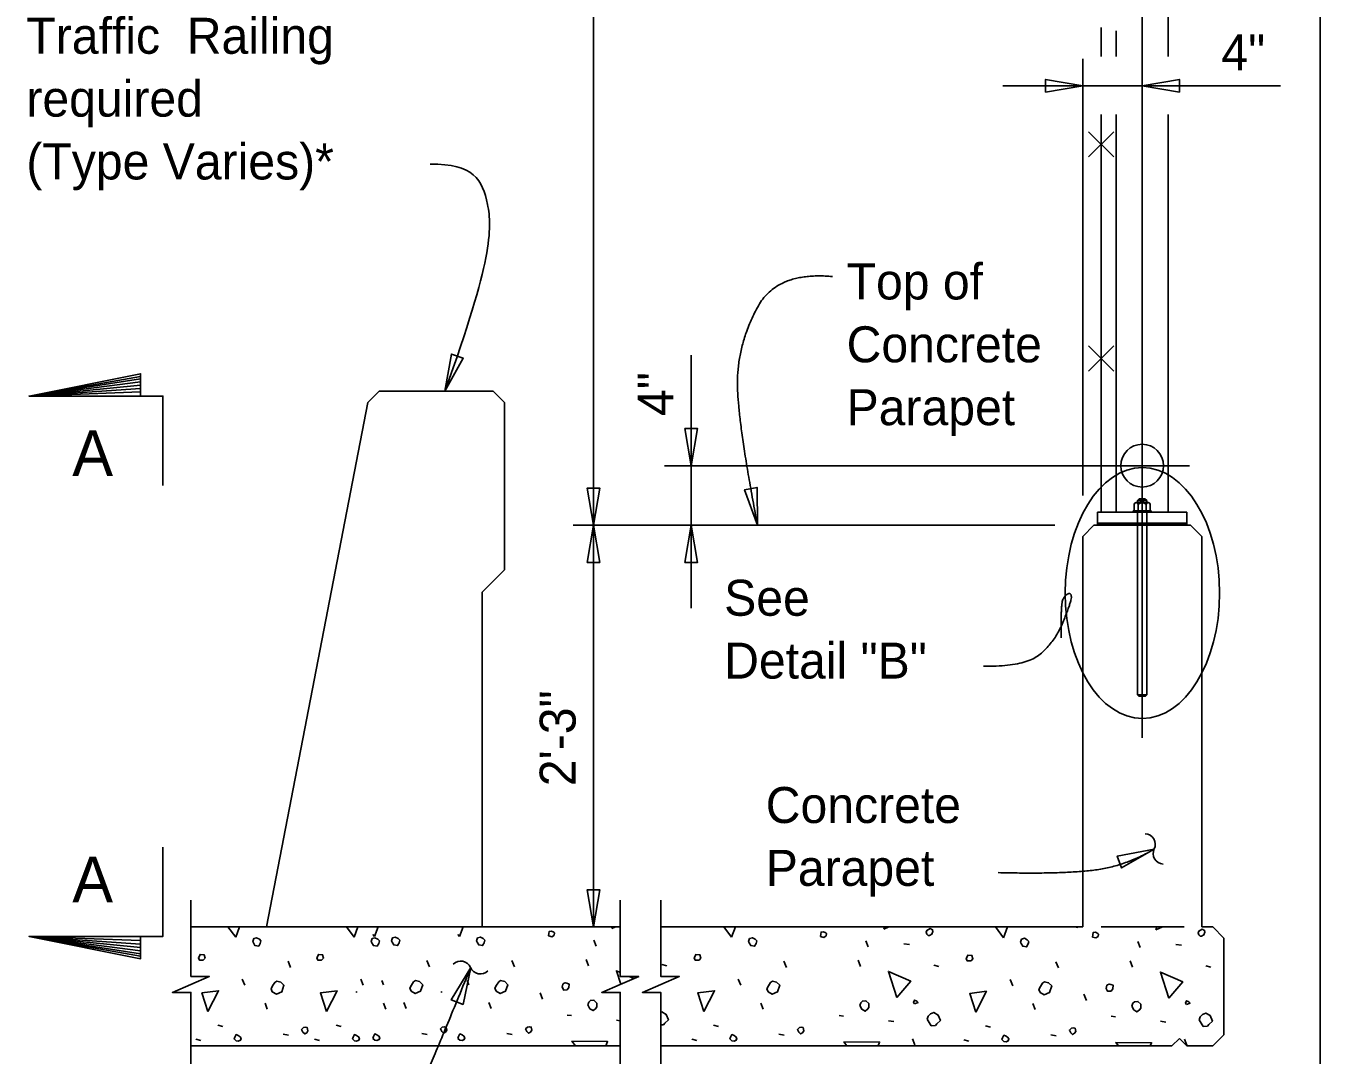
# Model space of a CAD drawing. Extents: x 0 to 72.1, y -15.2 to 30.1.
# Drawn here: x 33.82 to 41.07, y 15.56 to 21.32 of the extents above; entities that cross this region are included whole.
import ezdxf

# ---------------------------------------------------------------- set-up
doc = ezdxf.new("R2010")
doc.units = 0
for name, color, linetype in [('ActivePts-ConstElements', 7, 'Continuous'), ('AdhocPoint_dp', 7, 'Continuous'), ('Border', 7, 'Continuous'), ('Patterning', 7, 'Continuous'), ('PlotBorder_dp', 7, 'Continuous'), ('SheetBorder_dp', 7, 'Continuous'), ('SheetLines_dp', 7, 'Continuous'), ('SupstrConc_h', 7, 'Continuous'), ('TextMisc', 7, 'Continuous')]:
    doc.layers.add(name, color=color, linetype=linetype)

# ---------------------------------------------------------------- blocks, each defined once
blk = doc.blocks.new('Terminator-Arrow')
at = {"layer": 'PlotBorder_dp'}
blk.add_lwpolyline([(0, 0), (-0.00041, 0.000069), (-0.00041, -0.000069), (0, 0)], dxfattribs=at)
blk.add_lwpolyline([(0, 0), (-0.00041, 0.000069), (-0.00041, -0.000069)], close=True, dxfattribs=at)

msp = doc.modelspace()

# ---------------------------------------------------------------- linework, layer by layer
at = {"layer": 'ActivePts-ConstElements'}
msp.add_lwpolyline([(0.016, 2.0538), (41.0666, 2.0538), (41.0666, 27.9999), (0.016, 27.9999)], close=True, dxfattribs=at)
at = {"layer": 'AdhocPoint_dp'}
for p, q in [((39.7989, 18.5283), (39.7364, 18.465)), ((40.3405, 18.5283), (39.7989, 18.5283)), ((40.3405, 18.5283), (39.7989, 18.5283)), ((40.3405, 18.5283), (40.4031, 18.465)), ((39.7364, 16.2784), (39.7364, 18.465)), ((40.4031, 16.2784), (40.4031, 18.465)), ((34.7399, 16.2784), (37.1456, 16.2784)), ((37.3729, 16.2784), (39.7364, 16.2784)), ((40.4031, 16.2784), (40.4656, 16.2784)), ((40.4656, 16.2784), (40.5281, 16.2159)), ((40.5281, 16.2159), (40.5281, 15.6742)), ((40.5281, 15.6742), (40.4656, 15.6117)), ((40.2364, 15.6117), (37.3729, 15.6117)), ((40.2364, 15.6117), (40.2781, 15.6533)), ((40.2781, 15.6533), (40.3198, 15.6117)), ((40.4656, 15.6117), (40.3198, 15.6117))]:
    msp.add_line(p, q, dxfattribs=at)
at = {"layer": 'Border'}
for p, q in [((40.0437, 18.6013), (40.0437, 17.5781)), ((40.0958, 18.6013), (40.0958, 17.5781)), ((40.0437, 17.5781), (40.0958, 17.5781)), ((40.0437, 17.5781), (40.0519, 17.57)), ((40.0519, 17.57), (40.0876, 17.57)), ((40.0958, 17.5781), (40.0876, 17.57))]:
    msp.add_line(p, q, dxfattribs=at)
at = {"layer": 'Patterning'}
for p, q in [((39.9112, 20.7323), (39.7698, 20.5911)), ((39.7698, 20.7323), (39.9112, 20.5911)), ((39.9112, 19.5323), (39.7698, 19.3911)), ((39.7698, 19.5323), (39.9112, 19.3911)), ((40.0586, 18.6707), (40.0793, 18.6707)), ((40.0586, 18.661), (40.0793, 18.661)), ((39.8197, 18.5353), (40.3197, 18.5353)), ((39.8197, 18.5318), (40.3197, 18.5318)), ((35.4069, 16.2784), (35.4083, 16.2781)), ((38.185, 16.2784), (38.1863, 16.2781)), ((39.6911, 16.2784), (39.7101, 16.2746)), ((37.0108, 16.1703), (36.9984, 16.2039)), ((38.5346, 16.1667), (38.5222, 16.2003)), ((38.7343, 16.1826), (38.7662, 16.1791)), ((40.0584, 16.1632), (40.046, 16.1968)), ((40.2581, 16.1791), (40.29, 16.1756)), ((35.2987, 16.0518), (35.2845, 16.0872)), ((36.0762, 16.0554), (36.0621, 16.0907)), ((36.5529, 16.0554), (36.5388, 16.0907)), ((36.9683, 16.0607), (36.9542, 16.096)), ((37.3785, 16.0677), (37.4067, 16.0607)), ((38.0767, 16.0518), (38.0626, 16.0872)), ((38.4922, 16.0571), (38.478, 16.0925)), ((38.9023, 16.0642), (38.9306, 16.0571)), ((39.6005, 16.0483), (39.5864, 16.0836)), ((40.016, 16.0536), (40.0018, 16.0889)), ((40.4261, 16.0607), (40.4544, 16.0536)), ((35.0424, 15.9511), (35.0282, 15.9864)), ((35.7059, 15.9511), (35.6917, 15.9864)), ((35.8199, 15.9546), (35.8104, 15.9783)), ((36.2966, 15.9546), (36.2871, 15.9783)), ((37.8204, 15.9511), (37.8063, 15.9864)), ((39.3442, 15.9475), (39.3301, 15.9829)), ((36.7102, 15.8733), (36.6961, 15.9086)), ((39.7579, 15.8662), (39.7437, 15.9016)), ((35.1679, 15.8185), (35.1555, 15.8521)), ((35.8314, 15.8185), (35.819, 15.8521)), ((35.9454, 15.822), (35.933, 15.8556)), ((36.4221, 15.822), (36.4097, 15.8556)), ((37.9459, 15.8185), (37.9335, 15.8521)), ((39.4697, 15.8149), (39.4573, 15.8485)), ((36.8481, 15.7849), (36.8729, 15.7814)), ((37.1239, 15.7566), (37.1456, 15.7528)), ((38.3719, 15.7814), (38.3967, 15.7778)), ((38.6477, 15.7531), (38.6778, 15.7478)), ((39.8958, 15.7778), (39.9205, 15.7743)), ((40.1715, 15.7495), (40.2016, 15.7442)), ((34.8903, 15.7283), (34.9186, 15.7213)), ((35.2563, 15.6771), (35.2863, 15.6718)), ((35.5538, 15.7283), (35.5821, 15.7213)), ((36.0338, 15.6806), (36.0639, 15.6753)), ((36.5105, 15.6806), (36.5405, 15.6753)), ((37.6684, 15.7283), (37.6967, 15.7213)), ((38.0343, 15.6771), (38.0644, 15.6718)), ((39.1922, 15.7248), (39.2205, 15.7177)), ((39.5581, 15.6735), (39.5882, 15.6682)), ((34.7684, 15.6488), (34.7966, 15.6417)), ((35.4319, 15.6488), (35.4601, 15.6417)), ((37.5464, 15.6488), (37.5747, 15.6417)), ((38.7962, 15.6187), (38.7838, 15.6523)), ((39.0702, 15.6452), (39.0985, 15.6382)), ((40.32, 15.6152), (40.3076, 15.6488))]:
    msp.add_line(p, q, dxfattribs=at)
for points in [[(39.8406, 21.3159), (39.8406, 21.1537)], [(39.8406, 20.8291), (39.8406, 18.6013)], [(34.9911, 16.2215), (34.9479, 16.2784)], [(35.0123, 16.2784), (34.9911, 16.2215)], [(35.6546, 16.2215), (35.6114, 16.2784)], [(35.6758, 16.2784), (35.6546, 16.2215)], [(35.7886, 16.2784), (35.7686, 16.2251)], [(36.2652, 16.2784), (36.2453, 16.2251)], [(36.7438, 16.2286), (36.7633, 16.2233), (36.7757, 16.2321), (36.7774, 16.2445), (36.7739, 16.248), (36.7597, 16.2551), (36.7474, 16.2534), (36.7456, 16.241), (36.7438, 16.2286)], [(37.0992, 16.2693), (37.102, 16.2784)], [(37.1194, 16.2784), (37.0992, 16.2693)], [(37.3729, 16.2562), (37.3732, 16.2569), (37.3729, 16.2581)], [(37.7691, 16.2215), (37.7259, 16.2784)], [(37.7904, 16.2784), (37.7691, 16.2215)], [(38.2676, 16.2251), (38.2871, 16.2198), (38.2995, 16.2286), (38.3012, 16.241), (38.2977, 16.2445), (38.2836, 16.2516), (38.2712, 16.2498), (38.2694, 16.2374), (38.2676, 16.2251)], [(38.623, 16.2657), (38.6269, 16.2784)], [(38.6511, 16.2784), (38.623, 16.2657)], [(38.8705, 16.2304), (38.8775, 16.2304), (38.8917, 16.2374), (38.897, 16.2534), (38.8952, 16.2622), (38.8811, 16.2693), (38.8634, 16.2587), (38.8598, 16.248), (38.8634, 16.2374), (38.8705, 16.2304)], [(39.2929, 16.218), (39.2471, 16.2784)], [(39.3155, 16.2784), (39.2929, 16.218)], [(39.7915, 16.2215), (39.8109, 16.2162), (39.8233, 16.2251), (39.825, 16.2374), (39.8215, 16.241), (39.8074, 16.248), (39.795, 16.2463), (39.7932, 16.2339), (39.7915, 16.2215)], [(40.1468, 16.2622), (40.1518, 16.2784)], [(40.1828, 16.2784), (40.1468, 16.2622)], [(40.3943, 16.2268), (40.4013, 16.2268), (40.4155, 16.2339), (40.4208, 16.2498), (40.419, 16.2587), (40.4049, 16.2657), (40.3872, 16.2551), (40.3837, 16.2445), (40.3872, 16.2339), (40.3943, 16.2268)], [(35.0901, 16.1897), (35.0989, 16.1738), (35.1201, 16.1703), (35.129, 16.1862), (35.1325, 16.2003), (35.1237, 16.2092), (35.1078, 16.218), (35.0919, 16.2127), (35.0866, 16.1968), (35.0901, 16.1897)], [(35.7536, 16.1897), (35.7624, 16.1738), (35.7836, 16.1703), (35.7925, 16.1862), (35.796, 16.2003), (35.7872, 16.2092), (35.7713, 16.218), (35.7554, 16.2127), (35.7501, 16.1968), (35.7536, 16.1897)], [(35.7686, 16.2251), (35.7598, 16.2367)], [(35.8676, 16.1932), (35.8765, 16.1773), (35.8977, 16.1738), (35.9065, 16.1897), (35.9101, 16.2039), (35.9012, 16.2127), (35.8853, 16.2215), (35.8694, 16.2162), (35.8641, 16.2003), (35.8676, 16.1932)], [(36.2453, 16.2251), (36.2365, 16.2367)], [(36.3443, 16.1932), (36.3532, 16.1773), (36.3744, 16.1738), (36.3832, 16.1897), (36.3867, 16.2039), (36.3779, 16.2127), (36.362, 16.2215), (36.3461, 16.2162), (36.3408, 16.2003), (36.3443, 16.1932)], [(37.8681, 16.1897), (37.877, 16.1738), (37.8982, 16.1703), (37.907, 16.1862), (37.9106, 16.2003), (37.9017, 16.2092), (37.8858, 16.218), (37.8699, 16.2127), (37.8646, 16.1968), (37.8681, 16.1897)], [(39.3919, 16.1862), (39.4008, 16.1703), (39.422, 16.1667), (39.4308, 16.1826), (39.4344, 16.1968), (39.4255, 16.2056), (39.4096, 16.2145), (39.3937, 16.2092), (39.3884, 16.1932), (39.3919, 16.1862)], [(34.7878, 16.0925), (34.809, 16.0925), (34.8196, 16.1031), (34.8143, 16.1225), (34.7913, 16.1243), (34.7878, 16.1137), (34.7825, 16.1049), (34.7878, 16.0925), (34.7843, 16.096)], [(35.4513, 16.0925), (35.4725, 16.0925), (35.4831, 16.1031), (35.4778, 16.1225), (35.4548, 16.1243), (35.4513, 16.1137), (35.446, 16.1049), (35.4513, 16.0925), (35.4478, 16.096)], [(37.5658, 16.0925), (37.5871, 16.0925), (37.5977, 16.1031), (37.5924, 16.1225), (37.5694, 16.1243), (37.5658, 16.1137), (37.5605, 16.1049), (37.5658, 16.0925), (37.5623, 16.096)], [(39.0897, 16.0889), (39.1109, 16.0889), (39.1215, 16.0996), (39.1162, 16.119), (39.0932, 16.1208), (39.0897, 16.1102), (39.0844, 16.1013), (39.0897, 16.0889), (39.0861, 16.0925)], [(37.1483, 15.9574), (37.1239, 16.0324), (37.1456, 16.0229)], [(38.6954, 15.8821), (38.6477, 16.0288), (38.7732, 15.974), (38.6954, 15.8821)], [(40.2193, 15.8786), (40.1715, 16.0253), (40.297, 15.9705), (40.2193, 15.8786)], [(35.1962, 15.9139), (35.2191, 15.9016), (35.2492, 15.9139), (35.2616, 15.9511), (35.2439, 15.9687), (35.2209, 15.974), (35.2103, 15.967), (35.1979, 15.9475), (35.1891, 15.9316), (35.1962, 15.9139)], [(35.9737, 15.9175), (35.9967, 15.9051), (36.0267, 15.9175), (36.0391, 15.9546), (36.0214, 15.9723), (35.9984, 15.9776), (35.9878, 15.9705), (35.9755, 15.9511), (35.9666, 15.9352), (35.9737, 15.9175)], [(36.4504, 15.9175), (36.4734, 15.9051), (36.5034, 15.9175), (36.5158, 15.9546), (36.4981, 15.9723), (36.4751, 15.9776), (36.4645, 15.9705), (36.4522, 15.9511), (36.4433, 15.9352), (36.4504, 15.9175)], [(36.8198, 15.9405), (36.8287, 15.9245), (36.8481, 15.9263), (36.857, 15.9387), (36.8587, 15.9581), (36.8464, 15.9634), (36.8375, 15.9652), (36.8269, 15.9617), (36.8234, 15.9581), (36.8198, 15.9405)], [(37.1952, 16.0012), (37.222, 15.9895)], [(37.9742, 15.9139), (37.9972, 15.9016), (38.0272, 15.9139), (38.0396, 15.9511), (38.0219, 15.9687), (37.9989, 15.974), (37.9883, 15.967), (37.976, 15.9475), (37.9671, 15.9316), (37.9742, 15.9139)], [(39.498, 15.9104), (39.521, 15.898), (39.551, 15.9104), (39.5634, 15.9475), (39.5457, 15.9652), (39.5228, 15.9705), (39.5122, 15.9634), (39.4998, 15.944), (39.4909, 15.9281), (39.498, 15.9104)], [(39.8675, 15.9334), (39.8763, 15.9175), (39.8958, 15.9192), (39.9046, 15.9316), (39.9064, 15.9511), (39.894, 15.9564), (39.8851, 15.9581), (39.8745, 15.9546), (39.871, 15.9511), (39.8675, 15.9334)], [(34.8355, 15.8043), (34.8019, 15.9086), (34.8956, 15.921), (34.8355, 15.8043)], [(35.499, 15.8043), (35.4654, 15.9086), (35.5591, 15.921), (35.499, 15.8043)], [(35.6692, 15.9168), (35.6663, 15.9112)], [(36.1459, 15.9168), (36.143, 15.9112)], [(37.6136, 15.8043), (37.58, 15.9086), (37.6737, 15.921), (37.6136, 15.8043)], [(39.1374, 15.8008), (39.1038, 15.9051), (39.1975, 15.9175), (39.1374, 15.8008)], [(36.9648, 15.8415), (36.9754, 15.8202), (36.9931, 15.8096), (37.0072, 15.8202), (37.0143, 15.8309), (37.0143, 15.8521), (36.9984, 15.868), (36.9789, 15.8662), (36.9701, 15.8574), (36.9648, 15.8415)], [(38.4886, 15.8379), (38.4992, 15.8167), (38.5169, 15.8061), (38.531, 15.8167), (38.5381, 15.8273), (38.5381, 15.8485), (38.5222, 15.8644), (38.5028, 15.8627), (38.4939, 15.8538), (38.4886, 15.8379)], [(38.7944, 15.8468), (38.8139, 15.8556), (38.8068, 15.8627), (38.7944, 15.868), (38.7891, 15.8556), (38.7944, 15.8468)], [(40.0124, 15.8344), (40.023, 15.8132), (40.0407, 15.8026), (40.0549, 15.8132), (40.0619, 15.8238), (40.0619, 15.845), (40.046, 15.8609), (40.0266, 15.8591), (40.0177, 15.8503), (40.0124, 15.8344)], [(40.3183, 15.8432), (40.3377, 15.8521), (40.3306, 15.8591), (40.3183, 15.8644), (40.3129, 15.8521), (40.3183, 15.8432)], [(37.3729, 15.729), (37.3873, 15.7301), (37.3961, 15.7389), (37.4156, 15.7584), (37.4032, 15.7884), (37.3785, 15.8026), (37.3729, 15.8004)], [(38.8651, 15.7619), (38.8881, 15.7248), (38.9111, 15.7266), (38.9199, 15.7354), (38.9394, 15.7548), (38.927, 15.7849), (38.9023, 15.799), (38.8846, 15.792), (38.8705, 15.7778), (38.8651, 15.7619)], [(40.389, 15.7584), (40.4119, 15.7213), (40.4349, 15.723), (40.4438, 15.7319), (40.4632, 15.7513), (40.4508, 15.7814), (40.4261, 15.7955), (40.4084, 15.7884), (40.3943, 15.7743), (40.389, 15.7584)], [(34.9929, 15.6399), (35.0052, 15.6382), (35.0176, 15.6435), (35.0211, 15.6541), (35.0158, 15.6629), (35.0052, 15.67), (34.9929, 15.6753), (34.9858, 15.6611), (34.9823, 15.6505), (34.9929, 15.6399)], [(35.3676, 15.6894), (35.3782, 15.6788), (35.3888, 15.6859), (35.3959, 15.6965), (35.3924, 15.7142), (35.3835, 15.7159), (35.3712, 15.7142), (35.3606, 15.7036), (35.3676, 15.6894)], [(35.6564, 15.6399), (35.6687, 15.6382), (35.6811, 15.6435), (35.6846, 15.6541), (35.6793, 15.6629), (35.6687, 15.67), (35.6564, 15.6753), (35.6493, 15.6611), (35.6458, 15.6505), (35.6564, 15.6399)], [(35.7704, 15.6435), (35.7828, 15.6417), (35.7952, 15.647), (35.7987, 15.6576), (35.7934, 15.6665), (35.7828, 15.6735), (35.7704, 15.6788), (35.7633, 15.6647), (35.7598, 15.6541)], [(36.1452, 15.693), (36.1558, 15.6824), (36.1664, 15.6894), (36.1735, 15.7), (36.1699, 15.7177), (36.1611, 15.7195), (36.1487, 15.7177), (36.1381, 15.7071), (36.1452, 15.693)], [(36.2471, 15.6435), (36.2595, 15.6417), (36.2718, 15.647), (36.2754, 15.6576), (36.2701, 15.6665), (36.2595, 15.6735), (36.2471, 15.6788), (36.24, 15.6647), (36.2365, 15.6541)], [(36.6219, 15.693), (36.6325, 15.6824), (36.6431, 15.6894), (36.6501, 15.7), (36.6466, 15.7177), (36.6378, 15.7195), (36.6254, 15.7177), (36.6148, 15.7071), (36.6219, 15.693)], [(37.7709, 15.6399), (37.7833, 15.6382), (37.7957, 15.6435), (37.7992, 15.6541), (37.7939, 15.6629), (37.7833, 15.67), (37.7709, 15.6753), (37.7638, 15.6611), (37.7603, 15.6505), (37.7709, 15.6399)], [(38.1457, 15.6894), (38.1563, 15.6788), (38.1669, 15.6859), (38.174, 15.6965), (38.1704, 15.7142), (38.1616, 15.7159), (38.1492, 15.7142), (38.1386, 15.7036), (38.1457, 15.6894)], [(39.2947, 15.6364), (39.3071, 15.6346), (39.3195, 15.6399), (39.323, 15.6505), (39.3177, 15.6594), (39.3071, 15.6665), (39.2947, 15.6718), (39.2876, 15.6576), (39.2841, 15.647), (39.2947, 15.6364)], [(39.6695, 15.6859), (39.6801, 15.6753), (39.6907, 15.6824), (39.6978, 15.693), (39.6942, 15.7106), (39.6854, 15.7124), (39.673, 15.7106), (39.6624, 15.7), (39.6695, 15.6859)], [(35.7598, 15.6541), (35.7704, 15.6435)], [(36.2365, 15.6541), (36.2471, 15.6435)], [(36.8948, 15.6117), (36.8746, 15.6382), (37.0744, 15.6364), (37.0652, 15.6117)], [(38.4159, 15.6117), (38.3985, 15.6346), (38.5982, 15.6329), (38.5903, 15.6117)], [(39.9371, 15.6117), (39.9223, 15.6311), (40.122, 15.6293), (40.1154, 15.6117)]]:
    msp.add_lwpolyline(points, dxfattribs=at)
msp.add_lwpolyline([(39.8197, 18.5388), (40.3197, 18.5388), (40.3197, 18.5284), (39.8197, 18.5284)], close=True, dxfattribs=at)
at = {"layer": 'PlotBorder_dp'}
for p, q in [((36.9957, 16.2784), (36.9957, 24.8617)), ((39.7364, 18.694), (39.7364, 21.1397)), ((39.2898, 20.9897), (40.8444, 20.9897)), ((37.5436, 18.063), (37.5436, 19.4799)), ((33.8335, 19.2512), (34.4585, 19.3612)), ((34.4585, 19.3479), (33.8335, 19.2512)), ((33.8335, 19.2512), (34.4585, 19.3312)), ((34.4585, 19.3129), (33.8335, 19.2512)), ((33.8335, 19.2512), (34.4585, 19.2945)), ((34.4585, 19.2745), (33.8335, 19.2512)), ((40.0697, 18.609), (40.0697, 18.6083)), ((39.5803, 18.5284), (36.8819, 18.5284)), ((34.4585, 16.2016), (33.8335, 16.2249)), ((33.8335, 16.2249), (34.4585, 16.1816)), ((34.4585, 16.1633), (33.8335, 16.2249)), ((33.8335, 16.2249), (34.4585, 16.1449)), ((34.4585, 16.1283), (33.8335, 16.2249)), ((33.8335, 16.2249), (34.4585, 16.1149))]:
    msp.add_line(p, q, dxfattribs=at)
for points in [[(39.7364, 20.9897), (39.5282, 21.025), (39.5282, 20.9544)], [(40.0697, 20.9897), (40.278, 20.9544), (40.278, 21.025)], [(37.5436, 18.8617), (37.5789, 19.0699), (37.5083, 19.0699)], [(36.9957, 18.5284), (36.9604, 18.7366), (37.031, 18.7366)], [(37.9143, 18.5284), (37.9118, 18.7396), (37.8424, 18.727)], [(36.9957, 18.5284), (36.9604, 18.3201), (37.031, 18.3201)], [(37.5436, 18.5284), (37.5083, 18.3201), (37.5789, 18.3201)], [(40.1374, 16.7145), (39.93, 16.6749), (39.9546, 16.6088)], [(36.9957, 16.2784), (37.031, 16.4866), (36.9604, 16.4866)], [(36.3076, 16.0507), (36.1991, 15.8695), (36.2649, 15.8439)]]:
    msp.add_lwpolyline(points, close=True, dxfattribs=at)
for points in [[(34.5835, 18.7512), (34.5835, 19.2512), (33.8335, 19.2512), (34.4585, 19.3762), (34.4585, 19.2512)], [(34.5835, 16.7249), (34.5835, 16.2249), (33.8335, 16.2249), (34.4585, 16.0999), (34.4585, 16.2249)], [(34.7399, 16.4284), (34.7399, 16.0012), (34.8432, 16.0012), (34.7399, 15.9562), (34.6365, 15.9112), (34.7399, 15.9112), (34.7399, 15.4617)], [(37.1456, 16.4284), (37.1456, 16.0012), (37.249, 16.0012), (37.1456, 15.9562), (37.0423, 15.9112), (37.1456, 15.9112), (37.1456, 15.4617)], [(37.3729, 16.4284), (37.3729, 16.0012), (37.4763, 16.0012), (37.3729, 15.9562), (37.2696, 15.9112), (37.3729, 15.9112), (37.3729, 15.4617)]]:
    msp.add_lwpolyline(points, dxfattribs=at)
for centre, start, end in [((40.0832, 16.7407), 334.61622, 86.34344), ((40.1909, 16.6896), 154.61622, 266.34344), ((36.252, 16.0277), 22.88008, 134.6073), ((36.3619, 16.0741), 202.88008, 314.6073)]:
    msp.add_arc(centre, 0.0596, start, end, dxfattribs=at)
msp.add_ellipse((40.071, 18.1482), major_axis=(0, 0.7024), ratio=0.61552, dxfattribs=at)
for points, degree in [([(36.0807, 20.5498), (36.3226, 20.5557), (36.4287, 20.3667), (36.4287, 20.0125), (36.1633, 19.2784)], 3), ([(38.3343, 19.9207), (38.0205, 19.9513), (37.8022, 19.5356), (37.8022, 19.1164), (37.9143, 18.5284)], 2), ([(39.1809, 17.7384), (39.4075, 17.7344), (39.578, 17.8693), (39.6731, 18.0995), (39.6731, 18.1512), (39.6359, 18.1364), (39.6137, 18.0836), (39.6151, 17.8968)], 2), ([(39.262, 16.5822), (39.6006, 16.574), (39.9722, 16.6153), (40.1374, 16.7145)], 2), ([(36.2986, 15.0134), (36.0666, 14.9967), (35.9307, 15.1557), (36.0812, 15.4988), (36.3076, 16.0507)], 2)]:
    msp.add_open_spline(points, degree=degree, dxfattribs=at)
at = {"layer": 'SheetBorder_dp'}
for p, q in [((40.0698, 17.3367), (40.0698, 21.5561)), ((37.3936, 18.8617), (40.3354, 18.8617))]:
    msp.add_line(p, q, dxfattribs=at)
at = {"layer": 'SupstrConc_h'}
for p, q in [((35.163, 16.2784), (35.7323, 19.2158)), ((35.7323, 19.2158), (35.7948, 19.2783)), ((35.7948, 19.2783), (36.4338, 19.2784)), ((36.4338, 19.2783), (36.4963, 19.2158)), ((36.4963, 19.2158), (36.4963, 18.2783)), ((36.4963, 18.2783), (36.3713, 18.1533)), ((36.3713, 18.1533), (36.3713, 16.2784)), ((40.3045, 16.2784), (39.8394, 16.2784)), ((37.1456, 15.6117), (34.7399, 15.6117))]:
    msp.add_line(p, q, dxfattribs=at)
at = {"layer": 'TextMisc'}
for p, q in [((40.2156, 21.1537), (40.2156, 24.8617)), ((39.9239, 21.1537), (39.9239, 21.2978)), ((39.9239, 18.6013), (39.9239, 20.8291)), ((40.2156, 18.6013), (40.2156, 20.8291)), ((40.0243, 18.6459), (40.0243, 18.6083)), ((40.1038, 18.6546), (40.0357, 18.6546)), ((40.0537, 18.6756), (40.044, 18.6659)), ((40.044, 18.6659), (40.044, 18.6546)), ((40.044, 18.6659), (40.0955, 18.6659)), ((40.047, 18.6462), (40.047, 18.6083)), ((40.0537, 18.6756), (40.0842, 18.6756)), ((40.0842, 18.6756), (40.0955, 18.6659)), ((40.0924, 18.6462), (40.0924, 18.6083)), ((40.0955, 18.6659), (40.0955, 18.6546)), ((40.1151, 18.6459), (40.1151, 18.6083)), ((40.0201, 18.6083), (40.0201, 18.6012)), ((40.0201, 18.6083), (40.1195, 18.6083)), ((40.1151, 18.6083), (40.0243, 18.6083)), ((40.1195, 18.6083), (40.1195, 18.6012)), ((39.95, 18.5388), (40.1895, 18.5388))]:
    msp.add_line(p, q, dxfattribs=at)
msp.add_lwpolyline([(39.8197, 18.6013), (40.3197, 18.6013), (40.3197, 18.5388), (39.8197, 18.5388)], close=True, dxfattribs=at)
msp.add_circle((40.0698, 18.8617), 0.1198, dxfattribs=at)
for centre, radius, start, end in [((40.0357, 18.6428), 0.0118, 16.59863, 164.70054), ((40.0697, 18.6199), 0.0347, 49.20147, 130.79853), ((40.1037, 18.6429), 0.0118, 15.15064, 163.50417)]:
    msp.add_arc(centre, radius, start, end, dxfattribs=at)

# ---------------------------------------------------------------- block references
at = {"layer": 'PlotBorder_dp', "xscale": 507.9999699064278, "yscale": -507.99996990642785, "rotation": -109.44616743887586}
msp.add_blockref('Terminator-Arrow', (36.1633, 19.2784), dxfattribs=at)

# ---------------------------------------------------------------- texts
at = {"layer": 'PlotBorder_dp'}
for s, p in [('Traffic  Railing', (33.8184, 21.1688)), ('required', (33.8184, 20.8168)), ('(Type Varies)*', (33.8184, 20.4648)), ('Top of ', (38.4139, 19.7926)), ('Concrete', (38.4139, 19.4406)), ('Parapet', (38.4139, 19.0886)), ('See ', (37.7279, 18.0211)), ('Detail "B"', (37.7279, 17.6691)), ('Concrete', (37.9608, 16.8603)), ('Parapet', (37.9608, 16.5083))]:
    msp.add_text(s, height=0.2016, dxfattribs=at).set_placement(p)
at = {"layer": 'SheetLines_dp'}
for s, height, p in [('4"', 0.2016, (40.5134, 21.0766)), ('A', 0.256, (34.0756, 18.8045)), ('A', 0.256, (34.0756, 16.4158))]:
    msp.add_text(s, height=height, dxfattribs=at).set_placement(p)
for s, p in [('4"', (37.4439, 19.1402)), ('2\'-3"', (36.8957, 17.0665))]:
    msp.add_text(s, height=0.2016, rotation=90, dxfattribs=at).set_placement(p)

doc.saveas('drawing.dxf')
